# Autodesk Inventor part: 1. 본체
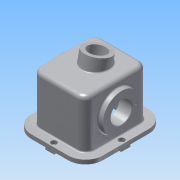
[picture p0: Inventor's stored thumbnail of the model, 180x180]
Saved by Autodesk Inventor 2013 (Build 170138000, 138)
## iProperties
Created: 2014-11
Part Number: 1. 본체
Material: 알루미늄 6061
Document SubType Name: Modeling
Designer: Administrator
Density: 1 g/cm^3
Author: Administrator
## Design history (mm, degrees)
sketch "스케치1"
  geometry: L1 (-45, 98)-(45, 98); L2 (87, 56)-(87, -56); L3 (45, -98)-(-45, -98); L4 (-87, -56)-(-87, 56); A1 r 42 centre (-45, 56) between (-45, 98) and (-87, 56); A2 r 42 centre (45, 56) between (87, 56) and (45, 98); A3 r 42 centre (45, -56) between (45, -98) and (87, -56); A4 r 42 centre (-45, -56) between (-87, -56) and (-45, -98); 1 further point
  constraints: 8 end point, 8 point on circle, 8 tangent, 4 centre point, 3 equal radius, 2 parallel, 1 horizontal, 1 perpendicular
extrude "돌출1" new body sketch "스케치1" distance "d3" = 10; taper "d4" = 0 deg
sketch "스케치2"
  geometry: L1 (-11, 78)-(11, 78); L2 (67, 11)-(67, -11); L3 (11, -78)-(-11, -78); L4 (-67, -11)-(-67, 11); L5 (11, 98)-(11, 78); L6 (-11, 98)-(-11, 78); L7 (-87, 11)-(-67, 11); L8 (-87, -11)-(-67, -11); L9 (-11, -78)-(-11, -98); L10 (11, -78)-(11, -98); L11 (67, 11)-(87, 11); L12 (67, -11)-(87, -11); L13 (-11, 98)-(11, 98); L14 (87, 11)-(87, -11); L15 (-87, 11)-(-87, -11); L16 (-11, -98)-(11, -98); 4 further points
  constraints: 32 end point, 3 perpendicular, 1 parallel
extrude "돌출2" join sketch "스케치2" distance "d11" = 5; taper "d12" = 0 deg
sketch "스케치3"
  geometry: L1 (-45, 76)-(45, 76); L2 (65, 56)-(65, -56); L3 (45, -76)-(-45, -76); L4 (-65, -56)-(-65, 56); A1 r 20 centre (-45, 56) between (-45, 76) and (-65, 56); A2 r 20 centre (45, 56) between (65, 56) and (45, 76); A3 r 20 centre (45, -56) between (45, -76) and (65, -56); A4 r 20 centre (-45, -56) between (-65, -56) and (-45, -76); 1 further point
  constraints: 8 end point, 8 point on circle, 8 tangent, 4 centre point, 3 equal radius, 2 parallel, 1 horizontal, 1 perpendicular
extrude "돌출3" join sketch "스케치3" distance "d16" = 118; taper "d17" = 0 deg
node "작업 평면1"
sketch "스케치4"
  geometry: L1 (-58, 56)-(-142.121, 73.88) reference; L2 (-118, 37.061)-(-148.566, 43.558); L3 (-148.566, 43.558)-(-142.121, 73.88); L4 (-118, 37.061)-(-111.555, 67.383)
  constraints: 8 end point, 2 perpendicular, 1 parallel, 1 point on line, 1 other
revolve "회전1" sketch "스케치4" stored, may be unused: angle "d23" = 90 deg
sketch "스케치5"
  geometry: L1 (-45, 66)-(45, 66); L2 (55, 56)-(55, -56); L3 (45, -66)-(-45, -66); L4 (-55, -56)-(-55, 56); A1 r 10 centre (45, 56) between (55, 56) and (45, 66); A2 r 10 centre (45, -56) between (45, -66) and (55, -56); A3 r 10 centre (-45, -56) between (-55, -56) and (-45, -66); A4 r 10 centre (-45, 56) between (-45, 66) and (-55, 56)
  constraints: 8 end point, 8 point on circle, 4 centre point
extrude "돌출4" cut sketch "스케치5" distance "d25" = 118; taper "d26" = 0 deg
sketch "스케치6"
  geometry: C1 r 45.5 at (-58, 56)
  constraints: 1 centre point
extrude "돌출5" join sketch "스케치6" distance "d29" = 12; taper "d30" = 0 deg
sketch "스케치7"
  geometry: C1 r 45.5 at (58, 56) reference
extrude "돌출6" join sketch "스케치7" distance "d31" = 12; taper "d32" = 0 deg
sketch "스케치8"
  geometry: C1 r 45.5 at (-68, 56) reference; 1 further point
extrude "돌출7" join sketch "스케치8" distance "d33" = 10; taper "d34" = -45 deg
sketch "스케치9"
  geometry: C1 r 45.5 at (68, 56) reference; 1 further point
extrude "돌출8" join sketch "스케치9" distance "d35" = 10; taper "d36" = -45 deg
sketch "스케치10"
  geometry: C1 r 26 at (0, 0); 1 further point
  constraints: 1 centre point
  dimensions: "d37" = 52 diameter of C1
extrude "돌출9" cut sketch "스케치10" stored distance "d38" = 10; taper "d39" = 0 deg
sketch "스케치11"
  geometry: L1 (-94.267, 63.709)-(-142.121, 73.88) reference; L2 (-108, 0)-(-108, 112) reference; L3 (-122.033, 48.142)-(-146.487, 53.339); L4 (-97.385, 49.036)-(-120.786, 54.01); L5 (-120.786, 54.01)-(-122.033, 48.142); L6 (-146.487, 53.339)-(-142.121, 73.88); L7 (-97.385, 49.036)-(-94.267, 63.709); 1 further point
  constraints: 12 end point, 4 parallel, 1 other
revolve "회전2" sketch "스케치11" stored, may be unused: angle "d45" = 90 deg
fillet "모깎기1" dims "d46" = 10
fillet "모깎기2" dims "d47" = 3
chamfer "모따기1" distance "d48" = 1; stored, may be unused: second distance "d49" = 2, angle "d50" = 45 deg
chamfer "모따기2" distance "d51" = 1; stored, may be unused: second distance "d52" = 2, angle "d53" = 45 deg
chamfer "모따기3" distance "d54" = 1; stored, may be unused: second distance "d55" = 2, angle "d56" = 45 deg
chamfer "모따기4" distance "d57" = 1; stored, may be unused: second distance "d58" = 2, angle "d59" = 45 deg
fillet "모깎기3" dims "d60" = 0.3
sketch "스케치12"
  geometry: L1 (88.505, 11.432)-(1.495, 11.432); L2 (1.495, 11.432)-(1.495, 40.568); L3 (1.495, 40.568)-(88.505, 40.568); L4 (88.505, 40.568)-(88.505, 11.432); 1 further point
  constraints: 2 other
extrude "돌출10" join sketch "스케치12" distance "d64" = 1; taper "d65" = 0 deg
sketch "스케치13"
  geometry: 7 further points
hole "구멍1" sketch "스케치13" at (0, 88), (77, 0), (-77, 0), (0, -88) diameter "d67" = 9; stored, may be unused: countersink angle "d71" = 90 deg, drill point angle "d73" = 118 deg; dims "d68" = 6, "d69" = 14, "d70" = 8.6, "d72" = 8
sketch "스케치14"
  geometry: 6 further points
  constraints: 5 other
  dimensions: "d77" = 360 deg dimension on point (0, 0) point (0, 35) (derived)
hole "구멍2" sketch "스케치14" at (0, 35), (-35, 0), (0, -35), (35, 0) diameter "d79" = 3.242; stored, may be unused: countersink angle "d83" = 90 deg, drill point angle "d85" = 118 deg; dims "d80" = 13, "d81" = 14, "d82" = 8.6, "d84" = 16
sketch "스케치15"
  geometry: 6 further points
  constraints: 5 other
  dimensions: "d89" = 360 deg dimension on point (0, 0) point (0, 35) (derived)
hole "구멍3" sketch "스케치15" at (0, 35), (-35, 0), (0, -35), (35, 0) diameter "d91" = 3.242; stored, may be unused: countersink angle "d95" = 90 deg, drill point angle "d97" = 118 deg; dims "d92" = 13, "d93" = 14, "d94" = 8.6, "d96" = 16
fillet "모깎기4" dims "d98" = 3
node "솔리드1"
other parameters: "d6" = 11, "d8" = 11, "d9" = 11, "d10" = 11
